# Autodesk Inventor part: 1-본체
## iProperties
Created: 2015-04
Part Number: 1-본체
Document SubType Name: Modeling
Designer: elite
Density: 2.71 g/cm^3
Material: 알루미늄-6061
Mass: 985.597 g
Surface Area: 1065.4 cm^2
Volume: 363.689 cm^3
Author: elite
